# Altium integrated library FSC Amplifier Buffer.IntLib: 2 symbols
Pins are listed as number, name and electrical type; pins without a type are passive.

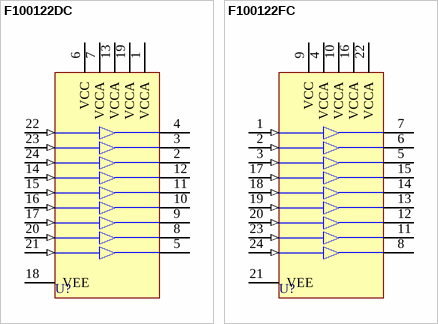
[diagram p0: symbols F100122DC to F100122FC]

## F100122DC
designator U?
9-Bit Buffer
footprint 6Y (DIP; 24 Leads; Row Spacing 10.16 mm; Pitch 2.54 mm)
3D model 6Y (DIP; 24 Leads; Row Spacing 10.16 mm; Pitch 2.54 mm)
pins: 1 VCCA (power), 2 O3 (oe), 3 O2 (oe), 4 O1 (oe), 5 O9 (oe), 6 VCC (power), 7 VCCA (power), 8 O8 (oe), 9 O7 (oe), 10 O6 (oe), 11 O5 (oe), 12 O4 (oe), 13 VCCA (power), 14 D4 (in), 15 D5 (in), 16 D6 (in), 17 D7 (in), 18 VEE (power), 19 VCCA (power), 20 D8 (in), 21 D9 (in), 22 D1 (in), 23 D2 (in), 24 D3 (in)

## F100122FC
designator U?
9-Bit Buffer
footprint 4V_N (CQFP, 24-Leads, Body 10x10mm; Pitch 1.27mm, Gullwing Leadform, IPC Medium Density)
footprint 4V_L (CQFP, 24-Leads, Body 10x10mm; Pitch 1.27mm, Gullwing Leadform, IPC High Density)
footprint 4V_M (CQFP, 24-Leads, Body 10x10mm; Pitch 1.27mm, Gullwing Leadform, IPC Low Density)
3D model F100122-4V (100-Pin Quad Cerpak 1.27 mm Pitch)
pins: 1 D1 (in), 2 D2 (in), 3 D3 (in), 4 VCCA (power), 5 O3 (oe), 6 O2 (oe), 7 O1 (oe), 8 O9 (oe), 9 VCC (power), 10 VCCA (power), 11 O8 (oe), 12 O7 (oe), 13 O6 (oe), 14 O5 (oe), 15 O4 (oe), 16 VCCA (power), 17 D4 (in), 18 D5 (in), 19 D6 (in), 20 D7 (in), 21 VEE (power), 22 VCCA (power), 23 D8 (in), 24 D9 (in)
